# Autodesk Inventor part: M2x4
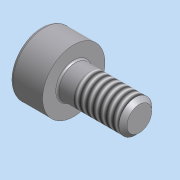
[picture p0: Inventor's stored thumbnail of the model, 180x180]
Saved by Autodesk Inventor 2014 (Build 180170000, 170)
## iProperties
Company: 한국ATC센터
Created: 2015-05
Part Number: M2x4
Document SubType Name: 모델링
Designer: KYOUNG IL JANG
Vendor: CBT Solutions
Material: 일반
Appearance: 기본값
Author: KYOUNG IL JANG
Comments: 파생
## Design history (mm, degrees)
node "KS B 1003 - 미터 M 2 x 4" dims "d0" = 10
node "솔리드1"
node "솔리드 본체"
node "곡면 본체"
feature "Solid1::KS B 1003 - 미터 M 2 x 4" dims "d0" = 10
tag "피쳐 태그1"
